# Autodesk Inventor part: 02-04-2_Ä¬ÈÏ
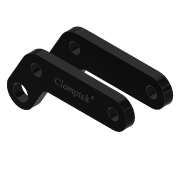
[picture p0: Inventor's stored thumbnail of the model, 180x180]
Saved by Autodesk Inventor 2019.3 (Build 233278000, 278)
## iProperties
Created: 2010-06
Part Number: 02-04-2_Ä¬ÈÏ
Material: Ogólny
Document SubType Name: Modeling
Designer: CADENGINEERING4
Density: 1 g/cm^3
Appearance: Gładki — czarny
Author: CADENGINEERING4
Revision Number: ÈÎºÎ
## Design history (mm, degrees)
feature "NONE"
feature "NONE:1"
node "Bryła1"
node "Bryła2"
